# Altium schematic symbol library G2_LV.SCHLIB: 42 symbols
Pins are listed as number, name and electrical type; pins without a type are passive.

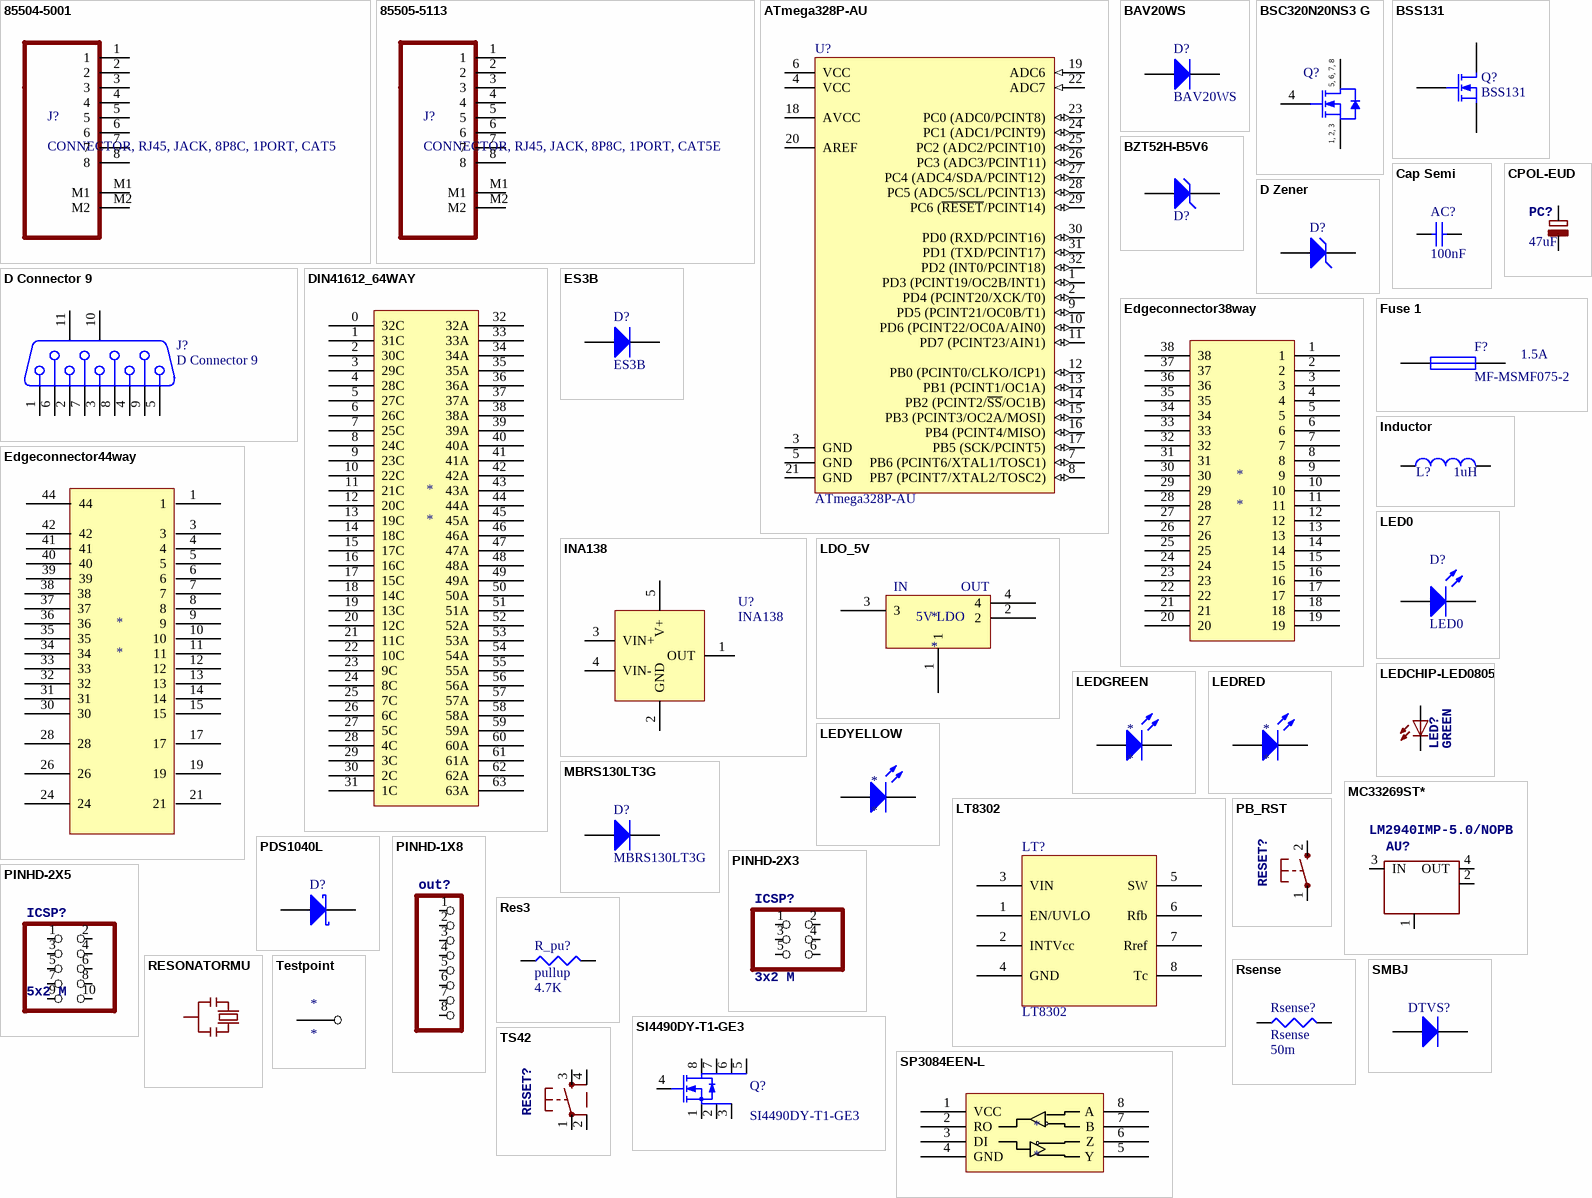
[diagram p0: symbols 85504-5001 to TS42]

## 85504-5001
designator J?, comment CONNECTOR, RJ45, JACK, 8P8C, 1PORT, CAT5
MPN: 85504-5001
footprint MOLEX_85504-5001
pins: 1, 2, 3, 4, 5, 6, 7, 8, M1, M2

## 85505-5113
designator J?, comment CONNECTOR, RJ45, JACK, 8P8C, 1PORT, CAT5E
MPN: 85505-5113
footprint MOLEX_85505-5113
pins: 1, 2, 3, 4, 5, 6, 7, 8, M1, M2

## ATmega328P-AU
designator U?
8-bit AVR Microcontroller, 32KB Flash, 1KB EEPROM, 2KB SRAM, 32-pin TQFP, Industrial Grade (-40°C to 85°C)
footprint 32A_N (Thin QFP, 32-Leads, Body 7x7mm, Pitch 0.8mm, IPC Medium Density)
footprint 32A_L (Thin QFP, 32-Leads, Body 7x7mm, Pitch 0.8mm, IPC High Density)
footprint 32A_M (Thin QFP, 32-Leads, Body 7x7mm, Pitch 0.8mm, IPC Low Density)
pins: 1 PD3 (PCINT19/OC2B/INT1) (io), 2 PD4 (PCINT20/XCK/T0) (io), 3 GND (power), 4 VCC (power), 5 GND (power), 6 VCC (power), 7 PB6 (PCINT6/XTAL1/TOSC1) (io), 8 PB7 (PCINT7/XTAL2/TOSC2) (io), 9 PD5 (PCINT21/OC0B/T1) (io), 10 PD6 (PCINT22/OC0A/AIN0) (io), 11 PD7 (PCINT23/AIN1) (io), 12 PB0 (PCINT0/CLKO/ICP1) (io), 13 PB1 (PCINT1/OC1A) (io), 14 PB2 (PCINT2/~{SS}/OC1B) (io), 15 PB3 (PCINT3/OC2A/MOSI) (io), 16 PB4 (PCINT4/MISO) (io), 17 PB5 (SCK/PCINT5) (io), 18 AVCC (power), 19 ADC6 (in), 20 AREF, 21 GND (power), 22 ADC7 (in), 23 PC0 (ADC0/PCINT8) (io), 24 PC1 (ADC1/PCINT9) (io), 25 PC2 (ADC2/PCINT10) (io), 26 PC3 (ADC3/PCINT11) (io), 27 PC4 (ADC4/SDA/PCINT12) (io), 28 PC5 (ADC5/SCL/PCINT13) (io), 29 PC6 (~{RESET}/PCINT14) (io), 30 PD0 (RXD/PCINT16) (io), 31 PD1 (TXD/PCINT17) (io), 32 PD2 (INT0/PCINT18) (io)

## BAV20WS
designator D?
Power Diode; Note: Pin 2 is not connected and not drawn.
footprint SOD-323
pins: 1 K, 2 A

## BSC320N20NS3 G
designator Q?
N-Channel OptiMOS 3 Power-Transistor, 200 V VDS, 36 A ID, -55 to 150 degC, PG-TDSON-8-1, Reel, Green; Manufacturer: Infineon; PartNumber: BSC320N20NS3 G; Green: TRUE; ID (max): 36 A; IDpuls (max): 144 A; Polarity: N; Ptot (max): 125 W; QG: 22 nC; RDS (on) (max): 32 mOhm; Rth: 1 K/W; RthJA (max): 1.5 K/W; RthJC (max): 62 K/W; VDS (max): 200 V; VGS(th) (max): 4 V; VGS(th) (min): 2 V
footprint INF-PG-TDSON-8-1_V (TDSON, 8-Leads, Body 6.15x5.15mm, Pitch 1.27mm)
pins: 1 SOURCE, 2 SOURCE, 3 SOURCE, 4 GATE, 5 DRAIN, 6 DRAIN, 7 DRAIN, 8 DRAIN

## BSS131
designator Q?
N-Channel MOSFET
footprint SOT-23
pins: 1 G, 2 S, 3 D

## BZT52H-B5V6
designator D?  (value not drawn)
Zener Diode
footprint SOD123F; pin to pad 1>2 2>1
pins: 1 A, 2 K

## Cap Semi
designator AC?  value 100nF  (hidden comment: Cap Semi)
Capacitor (Semiconductor SIM Model); PartNo: CC0603KRX7R9BB104
footprint C1206 (Chip Capacitor, Body 3.2x1.6mm, IPC High Density)
footprint 0402 (Chip Capacitor, Body 1.0x0.5mm, IPC High Density)
footprint C2512 (Chip Capacitor, Body 2.54x1.27mm, IPC High Density)
footprint 1608[0603] (Chip Capacitor, Body 1.6x0.8mm, IPC High Density)
footprint C1210 (Chip Capacitor, Body 3.2x2.5mm, IPC High Density)
simulation model CAP (Semiconductor Capacitor)
signal-integrity model Cap Semi
footprint 1812 (Chip Capacitor, Body 4.5x3.2mm, IPC High Density)
pins: 1, 2

## CPOL-EUD
designator PC?, comment value 47uF  (hidden comment: <B>POLARIZED CAPACITOR</B>, European symbol)
PartNo: EEE1EA470WAP
footprint PANASONIC_D
pins: 1, 2

## D Connector 9
designator J?
Receptacle Assembly, 9 Position, Right Angle; PartNo: 1734354-1; PackageDocument: O; Positions: 9
footprint DSUB1.385-2H9 (Connector; D Subminiature; 9 Position; Right Angle; Pitch 1.385 mm)
signal-integrity model Connector
pins: 1, 2, 3, 4, 5, 6, 7, 8, 9, 10 MH1, 11 MH2

## D Zener
designator D?, comment SMAJ30A  (value not drawn)
Zener Diode
footprint DIODE-0.7 (Diode, Thru-Hole; 2 Leads; 0.7 in Pin Spacing)
simulation model ZENER (Diode)
signal-integrity model D Zener
footprint DO-214AC
pins: 1 A, 2 K

## DIN41612_64WAY
designator *
footprint 09 03 164 6919
pins: 0 32C, 1 31C, 2 30C, 3 29C, 4 28C, 5 27C, 6 26C, 7 25C, 8 24C, 9 23C, 10 22C, 11 21C, 12 20C, 13 19C, 14 18C, 15 17C, 16 16C, 17 15C, 18 14C, 19 13C, 20 12C, 21 11C, 22 10C, 23 9C, 24 8C, 25 7C, 26 6C, 27 5C, 28 4C, 29 3C, 30 2C, 31 1C, 32 32A, 33 33A, 34 34A, 35 35A, 36 36A, 37 37A, 38 38A, 39 39A, 40 40A, 41 41A, 42 42A, 43 43A, 44 44A, 45 45A, 46 46A, 47 47A, 48 48A, 49 49A, 50 50A, 51 51A, 52 52A, 53 53A, 54 54A, 55 55A, 56 56A, 57 57A, 58 58A, 59 59A, 60 60A, 61 61A, 62 62A, 63 63A

## Edgeconnector38way
designator *
footprint FCIEdge; pin to pad 1>A1 2>A2 3>A3 4>A4 5>A5 6>A6 7>A7 8>A8 9>A9 10>A10 11>A11 12>A12 13>A13 14>A14 15>A15 16>A16 17>A17 18>A18 19>A19 20>B19 21>B18 22>B17 23>B16 24>B15 25>B14 26>B13 27>B12 28>B11 29>B10 30>B9 31>B8 32>B7 33>B6 34>B5 35>B4 36>B3 37>B2 38>B1
pins: 1, 2, 3, 4, 5, 6, 7, 8, 9, 10, 11, 12, 13, 14, 15, 16, 17, 18, 19, 20, 21, 22, 23, 24, 25, 26, 27, 28, 29, 30, 31, 32, 33, 34, 35, 36, 37, 38

## Edgeconnector44way
designator *
footprint 44wayPCBEdgeConnector
pins: 1, 3, 4, 5, 6, 7, 8, 9, 10, 11, 12, 13, 14, 15, 17, 19, 21, 24, 26, 28, 30, 31, 32, 33, 34, 35, 36, 37, 38, 39, 40, 41, 42, 44

## ES3B
designator D?
Power Diode; Note: Pin 2 is not connected and not drawn.
footprint DO-214AB
pins: 1 K, 2 A

## Fuse 1
designator F?, comment MF-MSMF075-2  Tripping current: 1.5A
Fuse; PartNo: MF-MSMF075/24-2
footprint PIN-W2/E2.8 (Thru-Hole; 2 Leads)
simulation model FUSE (Spice Subcircuit)
footprint MF-MSMF1
footprint MF-MSMF2
pins: 1, 2

## INA138
designator U?
PartNo: INA138NA/250
footprint SOT-23
pins: 1 OUT, 2 GND, 3 VIN+, 4 VIN-, 5 V+

## Inductor
designator L?  value 1uH  (hidden comment: Inductor)
PartNo: MPLC0730L1R0; Code_IEC: 1005
footprint MPLC0730
pins: 1, 2

## LDO_5V
designator *
PartNo: NCP1117ST50T3G
footprint SOT223
pins: 1, 2, 3, 4

## LED0
designator D?
Typical INFRARED GaAs LED
footprint LED-0 (LED; 2 Leads)
simulation model LED0 (Diode)
pins: 1 A, 2 K

## LEDCHIP-LED0805
designator LED?, comment GREEN
PartNo: KPT-2012SGC
footprint CHIP-LED0805
pins: A, C

## LEDGREEN
designator *
footprint LEDGREEN (LED; 2 Leads)
pins: 1 K, 2 A

## LEDRED
designator *
footprint LEDRED (LED; 2 Leads)
pins: 1 K, 2 A

## LEDYELLOW
designator *
footprint LEDYELLOW (LED; 2 Leads)
pins: 1 K, 2 A

## LT8302
designator LT?
PartNo: LT8302ES8E#PBF
footprint S8E
pins: 1 EN/UVLO, 2 INTVcc, 3 VIN, 4 GND, 5 SW, 6 Rfb, 7 Rref, 8 Tc

## MBRS130LT3G
designator D?
Power Diode; Note: Pin 2 is not connected and not drawn.
footprint SMB-403A
pins: 1 K, 2 A

## MC33269ST*
designator AU?, comment LM2940IMP-5.0/NOPB
1469076
footprint SOT223
pins: 1 GND/ADJ, 2 OUT, 3 IN, 4 OUT

## PB_RST
designator RESET?
PartNo: 1-1825027-4
footprint 1-1825027-4
pins: 1, 2

## PDS1040L
designator D?  (value not drawn)
Schottky Diode; PartNo: PDS1040L-13
footprint PDS1040L
pins: 1 A, 2 K

## PINHD-1X8
designator out?
PartNo: 5-534237-4
footprint 1X08
pins: 1, 2, 3, 4, 5, 6, 7, 8

## PINHD-2X3
designator ICSP?, comment 3x2 M
PartNo: M20-9980345
footprint 2X03
pins: 1, 2, 3, 4, 5, 6

## PINHD-2X5
designator ICSP?, comment 5x2 M
footprint 2X05
pins: 1, 2, 3, 4, 5, 6, 7, 8, 9, 10

## Res3
designator R_pu?, comment pullup  value 4.7K
Resistor
footprint J1-0603 (Chip Resistor, Body 1.6x0.8mm, IPC High Density)
footprint 14-1210 (Chip Resistor, Body 3.2x2.5mm, IPC High Density)
footprint 12Z-2010 (Chip Resistor, Body 5.0x2.5mm, IPC High Density)
footprint RESC6332 (Chip Resistor, Body 6.3x3.2mm, IPC High Density)
simulation model RESISTOR (Resistor)
signal-integrity model Res
footprint C1206 (Chip Capacitor, Body 3.2x1.6mm, IPC High Density)
pins: 1, 2

## RESONATORMU
designator Y?
PartNo: CSTCE16M0V53-R0
footprint RESONATOR
pins: 1, 2, 3

## Rsense
designator Rsense?  value 50m
CRF2512-FV-R001ELF; PartNo: MCS3264R050FER
footprint R6432
pins: 1, 2

## SI4490DY-T1-GE3
designator Q?
footprint SOIC-8
pins: 1 S, 2 S, 3 S, 4 G, 5 D, 6 D, 7 D, 8 D

## SMBJ
designator DTVS?, comment SMBJ24A-E3/52  (value not drawn)
TVS; Note: Pin 2 is not connected and not drawn.
footprint DO-214AA
pins: 1 K, 2 A

## SP3084EEN-L
designator *
footprint SOICN8
pins: 1 VCC, 2 RO, 3 DI, 4 GND, 5 Y, 6 Z, 7 B, 8 A

## Testpoint
designator *
footprint Testpoint_2.29mm
pins: 0

## TS42
designator RESET?
PartNo: B3S-1002
footprint B3S-1002
pins: 1, 2, 3, 4

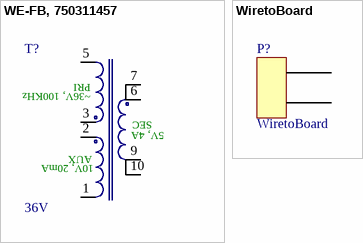
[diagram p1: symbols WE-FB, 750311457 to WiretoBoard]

## WE-FB, 750311457
designator T?, comment 36V
Flyback Transformer suitable or LT3573/ LT3574/ LT3575/ LT3748 WE-FB, Ui=36V; PartNo: 750311457; Manufacturer: Würth Elektronik eiSos GmbH
footprint EP13 (SMD, 10-Leads, Body 13.5x14.0mm (max), Pitch 2.48mm, IPC Medium Density)
pins: 1, 2, 3, 5, 6, 7, 9, 10

## WiretoBoard
designator P?
PartNo: 64T3402
footprint MC000044
pins: 1, 2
